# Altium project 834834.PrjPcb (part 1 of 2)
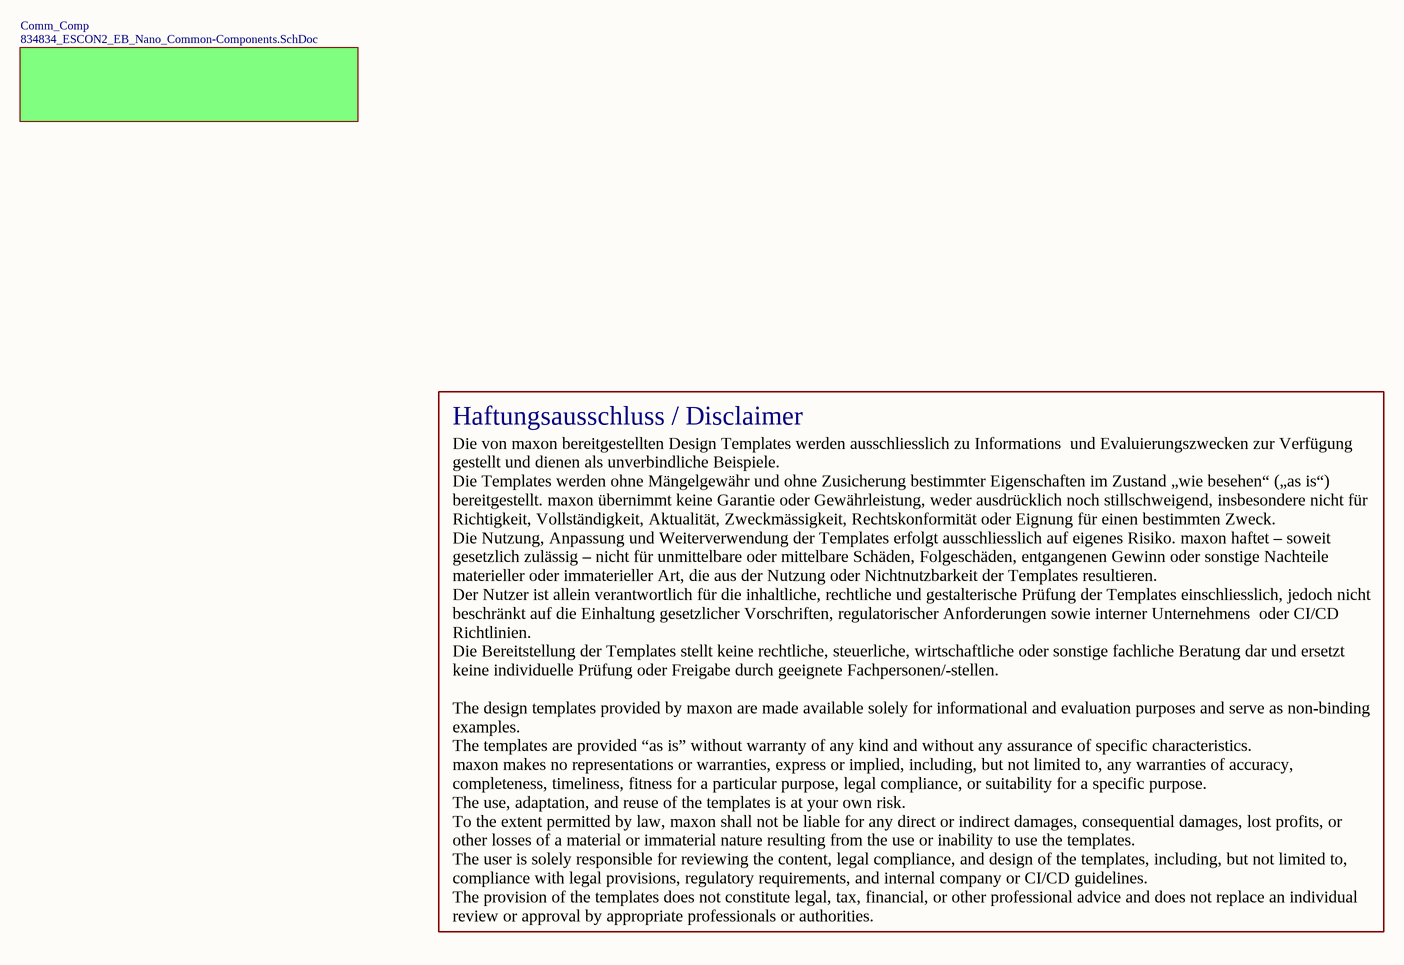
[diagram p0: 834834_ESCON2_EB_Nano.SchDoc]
PCB_raw: 834834-02; PCB unassembled: 834834; PCB Eng Rev: 02; Department: CCMC; CO_no: A100028401
4 sheets, 294 parts. Net scope: hierarchical (ports join the sheet entries above them; power ports are global).
Board file: ESCON2 EB Nano.PcbDoc
Sheets:
  834834_ESCON2_EB_Nano.SchDoc
    Comm_Comp = 834834_ESCON2_EB_Nano_Common-Components.SchDoc
      Nano_Comp = 834834_ESCON2_EB_Nano_Nano-Components.SchDoc
        Nano_CAN_RS422 = 834834_ESCON2_EB_Nano_Nano-CAN-RS422.SchDoc

## Sheet 834834_ESCON2_EB_Nano.SchDoc
size A3; SheetNumber: 1; SheetTotal: 4; Created: MMAGHIN; Modified: MMAGHIN; Reviewed: MMAGWAH; CreatedDate: 10.07.2023; ReviewedDate: 06.05.2024; ModifiedDate1: 29.04.2024

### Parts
*?  Disclaimer  (value not drawn)  (graphical)

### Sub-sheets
Comm_Comp = 834834_ESCON2_EB_Nano_Common-Components.SchDoc: no entries

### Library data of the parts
*? = CMP-002918-3: Disclaimer Text according to IFS-Doc:13538260

## Sheet 834834_ESCON2_EB_Nano_Common-Components.SchDoc
size A3; SheetNumber: 2; SheetTotal: 4; Created: MMAGHIN; Modified: MMAGHIN; Reviewed: MMAGWAH; CreatedDate: 10.07.2023; ReviewedDate: 06.05.2024; ModifiedDate1: 13.03.2024
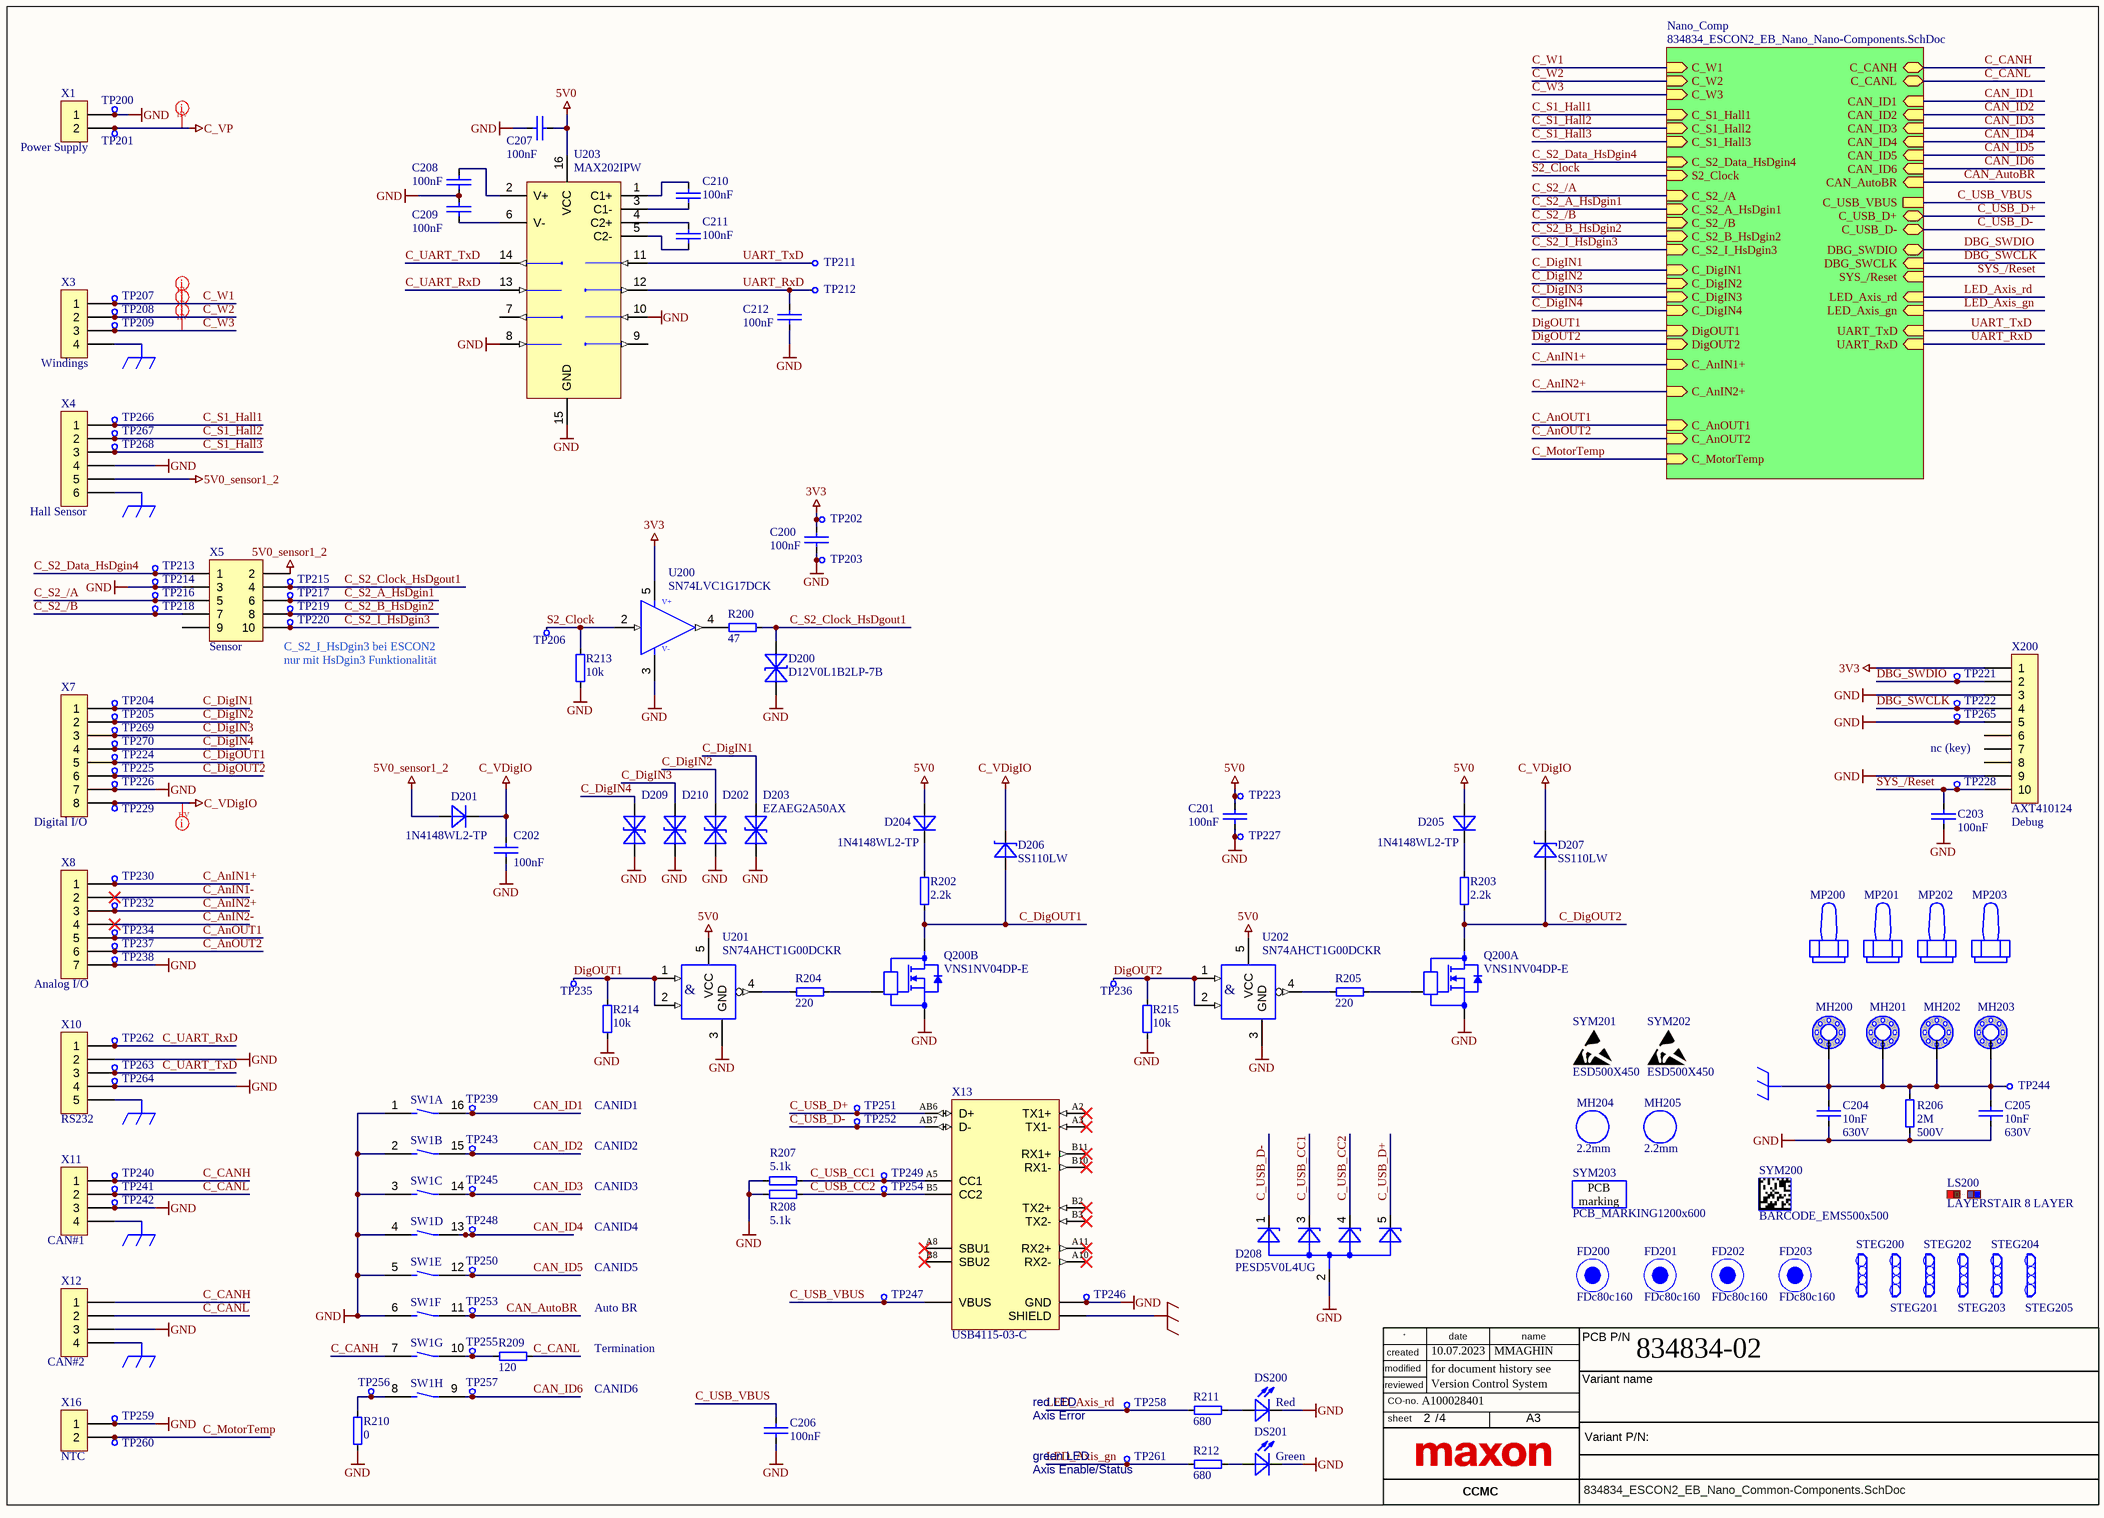
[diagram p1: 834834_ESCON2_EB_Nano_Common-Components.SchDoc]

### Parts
C200  value 100nF  [CAPC100X50X70L25N]  (hidden comment: 0402 100nF)
C201  value 100nF  [CAPC100X50X70L25N]  (hidden comment: 0402 100nF)
C202  value 100nF  [CAPC100X50X70L25N]  (hidden comment: 0402 100nF)
C203  value 100nF  [CAPC100X50X70L25N]  (hidden comment: 0402 100nF)
C204  value 10nF  Maximum Working Voltage: 630V  [CAPC200X125X150L47N]  (hidden comment: C0805C103KBRACAUTO)
C205  value 10nF  Maximum Working Voltage: 630V  [CAPC200X125X150L47N]  (hidden comment: C0805C103KBRACAUTO)
C206  value 100nF  [CAPC100X50X70L25N]  (hidden comment: 0402 100nF)
C207  value 100nF  [CAPC100X50X70L25N]  (hidden comment: 0402 100nF)
C208  value 100nF  [CAPC100X50X70L25N]  (hidden comment: 0402 100nF)
C209  value 100nF  [CAPC100X50X70L25N]  (hidden comment: 0402 100nF)
C210  value 100nF  [CAPC100X50X70L25N]  (hidden comment: 0402 100nF)
C211  value 100nF  [CAPC100X50X70L25N]  (hidden comment: 0402 100nF)
C212  value 100nF  [CAPC100X50X70L25N]  (hidden comment: 0402 100nF)
D200  D12V0L1B2LP-7B  [DIONPDFN2_102X60X60L25X50N]
D201  1N4148WL2-TP  [DIODFN2_102X60X60L25X50N]
D202  EZAEG2A50AX  [DIONPC105X53X43L26N]
D203  EZAEG2A50AX  [DIONPC105X53X43L26N]  (value not drawn)
D204  1N4148WL2-TP  [DIODFN2_102X60X60L25X50N]
D205  1N4148WL2-TP  [DIODFN2_102X60X60L25X50N]
D206  SS110LW  [SODFL359X170X143L65X95N]
D207  SS110LW  [SODFL359X170X143L65X95N]
D208  PESD5V0L4UG  [SOT23-5P65_210X110L28X20N]
D209  EZAEG2A50AX  [DIONPC105X53X43L26N]  (value not drawn)
D210  EZAEG2A50AX  [DIONPC105X53X43L26N]  (value not drawn)
DS200  Color(s): Red  [LEDSC80X160X90L45N_RED]  (hidden comment: 598-8010-107F)
DS201  Color(s): Green  [LEDSC80X160X90L45N_GREEN]  (hidden comment: 598-8070-107F)
FD200  FDc80c160  [FIDUCIAL_c80_c160]  (no BOM)
FD201  FDc80c160  [FIDUCIAL_c80_c160]  (no BOM)
FD202  FDc80c160  [FIDUCIAL_c80_c160]  (no BOM)
FD203  FDc80c160  [FIDUCIAL_c80_c160]  (no BOM)
LS200  LAYERSTAIR 8 LAYER  [8LS400X50w/oLETTERS_KEEPOUT]  (no BOM)
MH200  MTGNPH400A900V8H40_Snap-In_Spacer  [MTGNPH400A900V8H40_Snap-In_Spacer]  (value not drawn)  (no BOM)
MH201  MTGNPH400A900V8H40_Snap-In_Spacer  [MTGNPH400A900V8H40_Snap-In_Spacer]  (value not drawn)  (no BOM)
MH202  MTGNPH400A900V8H40_Snap-In_Spacer  [MTGNPH400A900V8H40_Snap-In_Spacer]  (value not drawn)  (no BOM)
MH203  MTGNPH400A900V8H40_Snap-In_Spacer  [MTGNPH400A900V8H40_Snap-In_Spacer]  (value not drawn)  (no BOM)
MH204  Diameter: 2.2mm  [MTGNPH220]  (hidden comment: MTGNPH220_NPTH)  (no BOM)
MH205  Diameter: 2.2mm  [MTGNPH220]  (hidden comment: MTGNPH220_NPTH)  (no BOM)
MP200  973100365  [WURTH_973100365]  (value not drawn)
MP201  973100365  [WURTH_973100365]  (value not drawn)
MP202  973100365  [WURTH_973100365]  (value not drawn)
MP203  973100365  [WURTH_973100365]  (value not drawn)
Q200  VNS1NV04DP-E  [SOIC8P127_490X599X175L83X41N]  (parts A,B of 2)
R200  value 47  [RESC100X52X40L22N]  (hidden comment: 0402 47R)
R202  value 2.2k  [RESC100X52X40L22N]  (hidden comment: 0402 2.2k)
R203  value 2.2k  [RESC100X52X40L22N]  (hidden comment: 0402 2.2k)
R204  value 220  [RESC100X52X40L22N]  (hidden comment: 0402 220R)
R205  value 220  [RESC100X52X40L22N]  (hidden comment: 0402 220R)
R206  value 2M  Maximum Working Voltage: 500V  [RESC320X160X90L47N]  (hidden comment: 1206 2M 500V)
R207  value 5.1k  [RESC100X52X40L22N]  (hidden comment: 0402 5.1k)
R208  value 5.1k  [RESC100X52X40L22N]  (hidden comment: 0402 5.1k)
R209  value 120  [RESC200X125X84L35N]  (hidden comment: 0805 120R)
R210  value 0  [RESC100X52X40L22N]  (hidden comment: 0402 0)
R211  value 680  [RESC100X52X40L22N]  (hidden comment: 0402 680R)
R212  value 680  [RESC100X52X40L22N]  (hidden comment: 0402 680R)
R213  value 10k  [RESC100X52X40L22N]  (hidden comment: 0402 10k)
R214  value 10k  [RESC100X52X40L22N]  (hidden comment: 0402 10k)
R215  value 10k  [RESC100X52X40L22N]  (hidden comment: 0402 10k)
STEG200  Steg400X90_7Hole  [Steg_400X90_7Hole]  (value not drawn)  (no BOM)
STEG201  Steg400X90_7Hole  [Steg_400X90_7Hole]  (value not drawn)  (no BOM)
STEG202  Steg400X90_7Hole  [Steg_400X90_7Hole]  (value not drawn)  (no BOM)
STEG203  Steg400X90_7Hole  [Steg_400X90_7Hole]  (value not drawn)  (no BOM)
STEG204  Steg400X90_7Hole  [Steg_400X90_7Hole]  (value not drawn)  (no BOM)
STEG205  Steg400X90_7Hole  [Steg_400X90_7Hole]  (value not drawn)  (no BOM)
SW1  DHN-08F-T-V  [SOIC16P127_1139X671X151L61X41N]  (value not drawn)  (parts A,B,C,D,E,F,G,H of 8)
SYM200  BARCODE_EMS500x500  [BARCODE_EMS_500x500]  (no BOM)
SYM201  ESD500X450  [ESD_copper_small]  (no BOM)
SYM202  ESD500X450  [ESD_copper_small]  (no BOM)
SYM203  PCB_MARKING1200x600  [MARKING_PCB_1200x600]  (no BOM)
TP200  TPc120  [TESTPOINT_c120]  (value not drawn)  (no BOM)
TP201  TPc120  [TESTPOINT_c120]  (value not drawn)  (no BOM)
TP202  TPc120  [TESTPOINT_c120]  (value not drawn)  (no BOM)
TP203  TPc120  [TESTPOINT_c120]  (value not drawn)  (no BOM)
TP204  TPc120  [TESTPOINT_c120]  (value not drawn)  (no BOM)
TP205  TPc120  [TESTPOINT_c120]  (value not drawn)  (no BOM)
TP206  TPc120  [TESTPOINT_c120]  (value not drawn)  (no BOM)
TP207  TPc120  [TESTPOINT_c120]  (value not drawn)  (no BOM)
TP208  TPc120  [TESTPOINT_c120]  (value not drawn)  (no BOM)
TP209  TPc120  [TESTPOINT_c120]  (value not drawn)  (no BOM)
TP211  TPc120  [TESTPOINT_c120]  (value not drawn)  (no BOM)
TP212  TPc120  [TESTPOINT_c120]  (value not drawn)  (no BOM)
TP213  TPc120  [TESTPOINT_c120]  (value not drawn)  (no BOM)
TP214  TPc120  [TESTPOINT_c120]  (value not drawn)  (no BOM)
TP215  TPc120  [TESTPOINT_c120]  (value not drawn)  (no BOM)
TP216  TPc120  [TESTPOINT_c120]  (value not drawn)  (no BOM)
TP217  TPc120  [TESTPOINT_c120]  (value not drawn)  (no BOM)
TP218  TPc120  [TESTPOINT_c120]  (value not drawn)  (no BOM)
TP219  TPc120  [TESTPOINT_c120]  (value not drawn)  (no BOM)
TP220  TPc120  [TESTPOINT_c120]  (value not drawn)  (no BOM)
TP221  TPc120  [TESTPOINT_c120]  (value not drawn)  (no BOM)
TP222  TPc120  [TESTPOINT_c120]  (value not drawn)  (no BOM)
TP223  TPc120  [TESTPOINT_c120]  (value not drawn)  (no BOM)
TP224  TPc120  [TESTPOINT_c120]  (value not drawn)  (no BOM)
TP225  TPc120  [TESTPOINT_c120]  (value not drawn)  (no BOM)
TP226  TPc120  [TESTPOINT_c120]  (value not drawn)  (no BOM)
TP227  TPc120  [TESTPOINT_c120]  (value not drawn)  (no BOM)
TP228  TPc120  [TESTPOINT_c120]  (value not drawn)  (no BOM)
TP229  TPc120  [TESTPOINT_c120]  (value not drawn)  (no BOM)
TP230  TPc120  [TESTPOINT_c120]  (value not drawn)  (no BOM)
TP232  TPc120  [TESTPOINT_c120]  (value not drawn)  (no BOM)
TP234  TPc120  [TESTPOINT_c120]  (value not drawn)  (no BOM)
TP235  TPc120  [TESTPOINT_c120]  (value not drawn)  (no BOM)
TP236  TPc120  [TESTPOINT_c120]  (value not drawn)  (no BOM)
TP237  TPc120  [TESTPOINT_c120]  (value not drawn)  (no BOM)
TP238  TPc120  [TESTPOINT_c120]  (value not drawn)  (no BOM)
TP239  TPc120  [TESTPOINT_c120]  (value not drawn)  (no BOM)
TP240  TPc120  [TESTPOINT_c120]  (value not drawn)  (no BOM)
TP241  TPc120  [TESTPOINT_c120]  (value not drawn)  (no BOM)
TP242  TPc120  [TESTPOINT_c120]  (value not drawn)  (no BOM)
TP243  TPc120  [TESTPOINT_c120]  (value not drawn)  (no BOM)
TP244  TPc120  [TESTPOINT_c120]  (value not drawn)  (no BOM)
TP245  TPc120  [TESTPOINT_c120]  (value not drawn)  (no BOM)
TP246  TPc120  [TESTPOINT_c120]  (value not drawn)  (no BOM)
TP247  TPc120  [TESTPOINT_c120]  (value not drawn)  (no BOM)
TP248  TPc120  [TESTPOINT_c120]  (value not drawn)  (no BOM)
TP249  TPc120  [TESTPOINT_c120]  (value not drawn)  (no BOM)
TP250  TPc120  [TESTPOINT_c120]  (value not drawn)  (no BOM)
TP251  TPc120  [TESTPOINT_c120]  (value not drawn)  (no BOM)
TP252  TPc120  [TESTPOINT_c120]  (value not drawn)  (no BOM)
TP253  TPc120  [TESTPOINT_c120]  (value not drawn)  (no BOM)
TP254  TPc120  [TESTPOINT_c120]  (value not drawn)  (no BOM)
TP255  TPc120  [TESTPOINT_c120]  (value not drawn)  (no BOM)
TP256  TPc120  [TESTPOINT_c120]  (value not drawn)  (no BOM)
TP257  TPc120  [TESTPOINT_c120]  (value not drawn)  (no BOM)
TP258  TPc120  [TESTPOINT_c120]  (value not drawn)  (no BOM)
TP259  TPc120  [TESTPOINT_c120]  (value not drawn)  (no BOM)
TP260  TPc120  [TESTPOINT_c120]  (value not drawn)  (no BOM)
TP261  TPc120  [TESTPOINT_c120]  (value not drawn)  (no BOM)
TP262  TPc120  [TESTPOINT_c120]  (value not drawn)  (no BOM)
TP263  TPc120  [TESTPOINT_c120]  (value not drawn)  (no BOM)
TP264  TPc120  [TESTPOINT_c120]  (value not drawn)  (no BOM)
TP265  TPc120  [TESTPOINT_c120]  (value not drawn)  (no BOM)
TP266  TPc120  [TESTPOINT_c120]  (value not drawn)  (no BOM)
TP267  TPc120  [TESTPOINT_c120]  (value not drawn)  (no BOM)
TP268  TPc120  [TESTPOINT_c120]  (value not drawn)  (no BOM)
TP269  TPc120  [TESTPOINT_c120]  (value not drawn)  (no BOM)
TP270  TPc120  [TESTPOINT_c120]  (value not drawn)  (no BOM)
U200  SN74LVC1G17DCK  [SOT23-5P65_210X110L28X20N]
U201  SN74AHCT1G00DCKR  [SOT23-5P65_210X110L28X20N]
U202  SN74AHCT1G00DCKR  [SOT23-5P65_210X110L28X20N]
U203  MAX202IPW  [SOP16P65_500X640X120L83X24N]
X1  39281023  [MOLEX_460150202]  (value not drawn)
X3  39281043  [MOLEX_460150402]  (value not drawn)
X4  430450612  [MOLEX_ 430450612]  (value not drawn)
X5  52601-S10-8LF  [AMPHENOL_52601-S10-8LF]  (value not drawn)
X7  5025840860  [MOLEX_5025840860]  (value not drawn)
X8  5025840760  [MOLEX_5025840760]  (value not drawn)
X10  RS232  [MOLEX_5025840560]
X11  5025840460  [MOLEX_5025840460]  (value not drawn)
X12  5025840460  [MOLEX_5025840460]  (value not drawn)
X13  USB4115-03-C  [GTC_USB4115-03-C]
X16  430450212  [MOLEX_ 430450212]  (value not drawn)
X200  AXT410124  [PANASONIC_AXT410124]

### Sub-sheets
Nano_Comp = 834834_ESCON2_EB_Nano_Nano-Components.SchDoc: C_W1 (in), C_W2 (in), C_W3 (in), C_S1_Hall1 (in), C_S1_Hall2 (in), C_S1_Hall3 (in), C_S2_Data_HsDgin4 (in), S2_Clock (in), C_S2_A_HsDgin1 (in), C_S2_B_HsDgin2 (in), C_S2_I_HsDgin3 (in), C_DigIN1 (in), C_DigIN2 (in), C_DigIN3 (in), C_DigIN4 (in), DigOUT1 (in), DigOUT2 (in), C_AnIN1+ (in), C_AnIN2+ (in), C_AnOUT1 (in), C_AnOUT2 (in), C_CANH (bidir), C_CANL (bidir), CAN_ID1 (in), CAN_ID2 (in), CAN_ID3 (in), CAN_ID4 (in), CAN_ID5 (in), CAN_ID6 (in), CAN_AutoBR (in), C_USB_VBUS, C_USB_D+ (bidir), C_USB_D- (bidir), DBG_SWDIO (bidir), DBG_SWCLK (in), SYS_/Reset (in), UART_TxD (in), UART_RxD (in), LED_Axis_rd (in), LED_Axis_gn (in), C_MotorTemp (in), C_S2_/B (in), C_S2_/A (in)

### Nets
3V3: C200.2 TP202.1 U200.5(VCC) X200.1
5V0: C201.2 C207.1 D204.2(A) D205.2(A) TP223.1 U201.5(VCC) U202.5(VCC) U203.16(VCC)
5V0_sensor1_2: D201.2(A) X4.5 X5.2
C_VDigIO: C202.2 D201.1(C) D206.1(C) D207.1(C) TP229.1 X7.8
C_VP: TP201.1 X1.2
GND: C200.1 C201.1 C202.1 C203.1 C204.1 C205.1 C206.1 C207.2 C208.1 C209.2 C212.1 D200.1 D202.1 D203.1 D208.2(A) D209.1 D210.1 DS200.1(C) DS201.1(C) Q200.1(S1) Q200.3(S2) R206.1 R207.2 R208.2 R210.1 R213.1 R214.1 R215.1 SW1.1 SW1.2 SW1.3 SW1.4 SW1.5 SW1.6 TP200.1 TP203.1 TP214.1 TP226.1 TP227.1 TP238.1 TP242.1 TP246.1 TP259.1 TP264.1 TP265.1 U200.3(GND) U201.3(GND) U202.3(GND) U203.8(RIN2) U203.10(DIN2) U203.15(GND) X1.1 X4.4 X5.3 X7.7 X8.7 X10.2 X10.4 X11.3 X12.3 X13.AB112(GND) X16.1 X200.3 X200.5 X200.9
SGND: C204.2 C205.2 MH200.1 MH201.1 MH202.1 MH203.1 R206.2 TP244.1 X3.4 X4.6 X10.5 X11.4 X12.4 X13.SHIELD
C_AnIN1+: TP230.1 X8.1 ; sheet Nano_Comp/C_AnIN1+
C_AnIN1-: X8.2
C_AnIN2+: TP232.1 X8.3 ; sheet Nano_Comp/C_AnIN2+
C_AnIN2-: X8.4
C_AnOUT1: TP234.1 X8.5 ; sheet Nano_Comp/C_AnOUT1
C_AnOUT2: TP237.1 X8.6 ; sheet Nano_Comp/C_AnOUT2
C_CANH: SW1.7 TP240.1 X11.1 X12.1 ; sheet Nano_Comp/C_CANH
C_CANL: R209.2 TP241.1 X11.2 X12.2 ; sheet Nano_Comp/C_CANL
C_DigIN1: D203.2 TP204.1 X7.1 ; sheet Nano_Comp/C_DigIN1
C_DigIN2: D202.2 TP205.1 X7.2 ; sheet Nano_Comp/C_DigIN2
C_DigIN3: D210.2 TP269.1 X7.3 ; sheet Nano_Comp/C_DigIN3
C_DigIN4: D209.2 TP270.1 X7.4 ; sheet Nano_Comp/C_DigIN4
C_DigOUT1: D206.2(A) Q200.5(D2) R202.1 TP224.1 X7.5
C_DigOUT2: D207.2(A) Q200.6(D1) R203.1 TP225.1 X7.6
C_MotorTemp: TP260.1 X16.2 ; sheet Nano_Comp/C_MotorTemp
C_S1_Hall1: TP266.1 X4.1 ; sheet Nano_Comp/C_S1_Hall1
C_S1_Hall2: TP267.1 X4.2 ; sheet Nano_Comp/C_S1_Hall2
C_S1_Hall3: TP268.1 X4.3 ; sheet Nano_Comp/C_S1_Hall3
C_S2_/A: TP216.1 X5.5 ; sheet Nano_Comp/C_S2_/A
C_S2_/B: TP218.1 X5.7 ; sheet Nano_Comp/C_S2_/B
C_S2_A_HsDgin1: TP217.1 X5.6 ; sheet Nano_Comp/C_S2_A_HsDgin1
C_S2_B_HsDgin2: TP219.1 X5.8 ; sheet Nano_Comp/C_S2_B_HsDgin2
C_S2_Clock_HsDgout1: D200.2 R200.2 TP215.1 X5.4
C_S2_Data_HsDgin4: TP213.1 X5.1 ; sheet Nano_Comp/C_S2_Data_HsDgin4
C_S2_I_HsDgin3: TP220.1 X5.10 ; sheet Nano_Comp/C_S2_I_HsDgin3
C_UART_RxD: TP262.1 U203.13(RIN1) X10.1
C_UART_TxD: TP263.1 U203.14(DOUT1) X10.3
C_USB_CC1: D208.3 R207.1 TP249.1 X13.A5(CC1)
C_USB_CC2: D208.4 R208.1 TP254.1 X13.B5(CC2)
C_USB_D+: D208.5 TP251.1 X13.AB6(D+) ; sheet Nano_Comp/C_USB_D+
C_USB_D-: D208.1 TP252.1 X13.AB7(D-) ; sheet Nano_Comp/C_USB_D-
C_USB_VBUS: C206.2 TP247.1 X13.AB49(VBUS) ; sheet Nano_Comp/C_USB_VBUS
C_W1: TP207.1 X3.1 ; sheet Nano_Comp/C_W1
C_W2: TP208.1 X3.2 ; sheet Nano_Comp/C_W2
C_W3: TP209.1 X3.3 ; sheet Nano_Comp/C_W3
CAN_AutoBR: SW1.11 TP253.1 ; sheet Nano_Comp/CAN_AutoBR
CAN_ID1: SW1.16 TP239.1 ; sheet Nano_Comp/CAN_ID1
CAN_ID2: SW1.15 TP243.1 ; sheet Nano_Comp/CAN_ID2
CAN_ID3: SW1.14 TP245.1 ; sheet Nano_Comp/CAN_ID3
CAN_ID4: SW1.13 TP248.1 ; sheet Nano_Comp/CAN_ID4
CAN_ID5: SW1.12 TP250.1 ; sheet Nano_Comp/CAN_ID5
CAN_ID6: SW1.9 TP257.1 ; sheet Nano_Comp/CAN_ID6
DBG_SWCLK: TP222.1 X200.4 ; sheet Nano_Comp/DBG_SWCLK
DBG_SWDIO: TP221.1 X200.2 ; sheet Nano_Comp/DBG_SWDIO
DigOUT1: R214.2 TP235.1 U201.1(inA) U201.2(inB) ; sheet Nano_Comp/DigOUT1
DigOUT2: R215.2 TP236.1 U202.1(inA) U202.2(inB) ; sheet Nano_Comp/DigOUT2
LED_Axis_gn: R212.1 TP261.1 ; sheet Nano_Comp/LED_Axis_gn
LED_Axis_rd: R211.1 TP258.1 ; sheet Nano_Comp/LED_Axis_rd
S2_Clock: R213.2 TP206.1 U200.2(inA) ; sheet Nano_Comp/S2_Clock
SYS_/Reset: C203.2 TP228.1 X200.10 ; sheet Nano_Comp/SYS_/Reset
UART_RxD: C212.2 TP212.1 U203.12(ROUT1) ; sheet Nano_Comp/UART_RxD
UART_TxD: TP211.1 U203.11(DIN1) ; sheet Nano_Comp/UART_TxD
NetC208_2: C208.2 U203.2(V+)
NetC209_1: C209.1 U203.6(V-)
NetC210_1: C210.1 U203.1(C1+)
NetC210_2: C210.2 U203.3(C1-)
NetC211_1: C211.1 U203.4(C2+)
NetC211_2: C211.2 U203.5(C2-)
NetD204_1: D204.1(C) R202.2
NetD205_1: D205.1(C) R203.2
NetDS200_2: DS200.2(A) R211.2
NetDS201_2: DS201.2(A) R212.2
NetQ200_2: Q200.2(IN1) R205.2
NetQ200_4: Q200.4(IN2) R204.2
NetR200_1: R200.1 U200.4(outY)
NetR204_1: R204.1 U201.4(outY)
NetR205_1: R205.1 U202.4(outY)
NetR209_1: R209.1 SW1.10 TP255.1
NetR210_2: R210.2 SW1.8 TP256.1

Not connected (* = marked no-connect by the designer): U203 7(DOUT2) 9(ROUT2); X5 9; X13 A2(TX1+)* A3(TX1-)* A8(SBU1)* A10(RX2-)* A11(RX2+)* B2(TX2+)* B3(TX2-)* B8(SBU2)* B10(RX1-)* B11(RX1+)*; X200 6 7 8

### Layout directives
net class HV: C_VDigIO, C_VP, C_W1, C_W2, C_W3

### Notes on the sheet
- Power Supply
- (near X3) Windings
- (near X4) Hall Sensor
- (near X5) Sensor
- C_S2_I_HsDgin3 bei ESCON2
- nur mit HsDgin3 Funktionalität
- nc (key)
- Digital I/O
- (near X200) Debug
- (near X8) Analog I/O
- CANID1
- CANID2
- CANID3
- (near X11) CAN#1
- CANID4
- CANID5
- Auto BR
- (near X12) CAN#2
- CANID6
- Termination
- (near X16) NTC
- red LED
- Axis Error
- green LED
- Axis Enable/Status

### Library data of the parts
C200 C201 C203 C207-C212 = CMP-000709-3: 100nF X7R >=16V 20%; Part Number: Ceramic, 0402, 100nF, 20%, >=16V, X7R, @, Soft Termination: N, -55°C to 125°C; Manufacturer: X; Maximum Working Voltage: 16V; Soft Termination: N; Case (Metric): 1005
C202 C206 = CMP-001306-1: 100nF X7R >=50V 20%; Part Number: Ceramic, 0402, 100nF, 20%, >=50V, X7R, @, Soft Termination: N, -55°C to 125°C; Manufacturer: X; Soft Termination: N; Case (Metric): 1005; Maximum Working Voltage: 50V
C204 C205 = CMP-000937-4: 10nF X7R >=630V 20%; Manufacturer: Murata; Dielectric Withstanding Voltage: > 850V 1sec; Case (Metric): 2012; Soft Termination: N
D200 = CMP-001106-5: Transient Voltage Suppressor Diode, 12V V(RWM), Bidirectional, 100W, 1 Element, SOD-882/DFN1006; Manufacturer: Diodes; Element Configuration: Single; Breakdown Voltage: 13V; Polarity: Bipolar
D201 D204 D205 = CMP-000606-13: Diode Switching, >=70V, >=150mA, SOD882/DFN1006/0402/SOD-923F; Manufacturer: MCC; Polarity: Unipolar; Recovery time: 4ns; Reverse Voltage: 70V; Element Configuration: Single; RMS Current: 150mA
D202 D203 D209 D210 = CMP-000066-17: Transient Voltage Suppressor Diode, 30V V(RWM), Bidirectional, ESD, 1 Element, 0402; Manufacturer: Panasonic; Element Configuration: Single; Polarity: Bipolar
D206 D207 = CMP-000633-9: Schottky Diode, >=90V, >=1A, SOD-123FL/SOD-123W; Manufacturer: Taiwan Semiconductor; RMS Current: 1A; Polarity: Unipolar; Reverse Voltage: 90V; Element Configuration: Single
D208 = CMP-000635-10: Transient Voltage Suppressor Diode, 4-Line, 5V V(RWM), Unidirectional, 30W, 4 Element , SOT353/SC-88A; Manufacturer: Nexperia; Min Breakdown Voltage: 6.46V; Nummber of Pins: 5; Element Configuration: Array; Common Anode; Max Junction Temperature: 150°C; Polarity: Unipolar; Breakdown Voltage: 6.8V; Nummber of Elements: 4; Max Breakdown Voltage: 7.14V; Clamping Voltage: 12V
DS200 = CMP-000723-7: Single Color Chip LED, red, 0603; Manufacturer: Dialight; Luminous Intensity: >5mcd@20mA; Wavelength: 617-640nm
DS201 = CMP-000722-6: Single Color Chip LED, green, 0603; Manufacturer: Dialight; Luminous Intensity: >5mcd@20mA; Wavelength: 564...575nm
FD200-FD203 = CMP-000010-5: Fiducial, Global, Round; 0.80 mm D, 1.60 mm Clearance
LS200 = CMP-001088-3: Layer Stair 8 Layer
MH200-MH203 = CMP-001801-1: Mounting Hole, Non-Plated; 9.00 mm Clearance, 4.00 mm Hole (with 8 vias), for 4mm Dia. Snap-In Spacer; pin to pad: 1>2+3+4+5+6+7+8+9; Metric screw: 4mm Dia Snap-In Spacer; Wave: X
MH204 MH205 = CMP-001004-5: Mounting Hole, Non-Plated; 0.00 mm Clearance, 2.20 mm Hole
MP200-MP203 = CMP-001759-4: WA-SNTI Plastic Spacer Stud, D=4.0mm, L=10mm, M3, SW=6; Min PCB Thickness: 1.8mm; Max PCB Thickness: 2.1mm; Mounting Hole Diameter: 4.00mm; Stand-Off Height: 10mm; Stand-Off Outside Size: SW6; Connection Style PCB Side: Snap; Connection Diameter PCB Side: 4.0mm; Connection Style Far Side: Female; Connection Length Far Side: 5mm; Stand-Off Outside Style: Hex; Connection Length PCB Side: 9.5mm
Q200 = CMP-001108-5: N-Channel MOSFET, Self Protected, 36V, 0.5ohm, SO-8; pin to pad: 5>5+6 6>7+8; Manufacturer: ST Microelectronics; Element Configuration: N-CH, Self Protected
R200 = CMP-000161-11: 47R 1% 62.5mW 100ppm; Part Number: Thick-Film, 0402, 47, 1%, 62.5mW@70°C, 50V, 100ppm, -55°C to 155°C; Manufacturer: X; Max Junction Temperature: 155°C; AECQ: N; Case (Metric): 1050; Power Rating Temperature: 70°C; Maximum Working Voltage: 50V; Maximum Overload Voltage: 100V
R202 R203 = CMP-000197-11: 2.2k 1% 62.5mW 100ppm; Part Number: Thick-Film, 0402, 2.2k, 1%, 62.5mW@70°C, 50V, 100ppm, -55°C to 155°C; Manufacturer: X; Max Junction Temperature: 155°C; AECQ: N; Case (Metric): 1050; Power Rating Temperature: 70°C; Maximum Working Voltage: 50V; Maximum Overload Voltage: 100V
R204 R205 = CMP-000173-11: 220R 1% 62.5mW 100ppm; Part Number: Thick-Film, 0402, 220, 1%, 62.5mW@70°C, 50V, 100ppm, -55°C to 155°C; Manufacturer: X; Max Junction Temperature: 155°C; AECQ: N; Case (Metric): 1050; Power Rating Temperature: 70°C; Maximum Working Voltage: 50V; Maximum Overload Voltage: 100V
R206 = CMP-000935-4: 2M 5% 250mW 200ppm >=500V; Manufacturer: X; Part Number: Thick-Film, 1206, 2M, 5%, 250mW@70°C, 500V, 200ppm, -55°C to 155°C; AECQ: N; Case (Metric): 3216; Maximum Overload Voltage: 1kV; Power Rating Temperature: 70°C; Max Junction Temperature: 155°C
R207 R208 = CMP-000206-11: 5.1k 1% 62.5mW 100ppm; Part Number: Thick-Film, 0402, 5.1k, 1%, 62.5mW@70°C, 50V, 100ppm, -55°C to 155°C; Manufacturer: X; Max Junction Temperature: 155°C; AECQ: N; Case (Metric): 1050; Power Rating Temperature: 70°C; Maximum Working Voltage: 50V; Maximum Overload Voltage: 100V
R209 = CMP-000325-10: 120R 1% 125mW 100ppm; Part Number: Thick-Film, 0805, 120, 1%, 125mW@70°C, 150V, 100ppm, -55°C to 155°C; Manufacturer: X; Max Junction Temperature: 155°C; AECQ: N; Case (Metric): 2012; Power Rating Temperature: 70°C; Maximum Working Voltage: 150V; Maximum Overload Voltage: 300V
R210 = CMP-000466-10: 0R Jumper; Part Number: Thick-Film, 0402, 0, -55°C to 155°C; Manufacturer: X; Case (Metric): 1050; RMS Current: 1A; Maximum Overload Voltage: 100V; Max Junction Temperature: 155°C; Maximum Working Voltage: 50V
R211 R212 = CMP-000185-11: 680R 1% 62.5mW 100ppm; Part Number: Thick-Film, 0402, 680, 1%, 62.5mW@70°C, 50V, 100ppm, -55°C to 155°C; Manufacturer: X; Max Junction Temperature: 155°C; AECQ: N; Case (Metric): 1050; Power Rating Temperature: 70°C; Maximum Working Voltage: 50V; Maximum Overload Voltage: 100V
R213-R215 = CMP-000492-11: 10k 1% 62.5mW 100ppm; Part Number: Thick-Film, 0402, 10k, 1%, 62.5mW@70°C, 50V, 100ppm, -55°C to 155°C; Manufacturer: X; Max Junction Temperature: 155°C; AECQ: N; Case (Metric): 1050; Power Rating Temperature: 70°C; Maximum Working Voltage: 50V; Maximum Overload Voltage: 100V
STEG200-STEG205 = CMP-000007-5: Breakaway tabs; 4.00 mm L X 0.90 mm W, 7 Hole
SW1 = CMP-001031-3: Slide Dip Switch, 8 Switches, 0.025A, 24VDC, SMD; Manufacturer: Diptronics
SYM200 = CMP-001233-2: Barcode EMS; 5.0 x 5.0 mm
SYM201 SYM202 = CMP-000018-6: ESD-Sign; 5.0 mm L X 4.5 mm W
SYM203 = CMP-001854-7: PCB Marking; 12.0 x 6.0 mm
TP200-TP209 TP211-TP230 TP232 TP234-TP270 = CMP-000014-7: Test Point; 1 pin, 1.20 mm D
U200 = CMP-001041-6: Single buffer with Schmitt-Trigger inputs; Manufacturer: Texas Instruments; AECQ: N; Max Supply Voltage: 5.5V; Min Supply Voltage: 1.65V
U201 U202 = CMP-002037-1: Single, 2-Input NAND Gate, 5V; Min Supply Voltage: 4.5V; Max Supply Voltage: 5.5V
U203 = CMP-000646-4: RS-232 Line Transceiver, Dual channel 120kbps , 5.0V, TSSOP16; Manufacturer: Texas instruments; Max Supply Voltage: 5.5V; Min Supply Voltage: 4.5V
X1 = CMP-001018-6: Mini-Fit Jr. Vertical Header, 4.20mm Pitch, Dual Row, 2 Circuits, without Snap-in Plastic Peg PCB Lock, Tin, Natural; Number of Contacts: 2; Operating Voltage: 600V; Operating Current: 9A; System: Connector
X3 = CMP-001016-8: Mini-Fit Jr. Vertical Header, 4.20mm Pitch, Dual Row, 4 Circuits, without Snap-in Plastic Peg PCB Lock, Tin, Natural; Operating Current: 9A; Operating Voltage: 600V; Number of Contacts: 4; System: Connector
X4 = CMP-001098-6: Micro-Fit 3.0 Vertical Header, 3.00mm Pitch, Dual Row, 6 Circuits, with PCB Polarizing Peg, Black; Manufacturer: Molex; Operating Voltage: 600V; Number of Contacts: 6; Operating Current: 8.5A
X5 = CMP-001165-3: Header, 2.54mm Pitch, Dual Row, SMT, Vertical, 10 Circuits; Manufacturer: Amphenol; Operating Voltage: 500V; Number of Contacts: 10; Operating Current: 3A
X7 = CMP-001014-7: 1.50mm Pitch, CLIK-Mate PCB Receptacle, Single Row, Surface Mount, Tin Plating, Positive Lock, with Pick-and-Place Polyimide Tape, 8 Circuits, Beige; Manufacturer: Molex; Number of Contacts: 8; Operating Current: 2A; Operating Voltage: 100V
X8 = CMP-001015-7: 1.50mm Pitch, CLIK-Mate PCB Receptacle, Single Row, Surface Mount, Tin Plating, Positive Lock, with Pick-and-Place Polyimide Tape, 7 Circuits, Beige; Manufacturer: Molex; Operating Voltage: 100V; Operating Current: 2A; Number of Contacts: 7
X10 = CMP-001023-6: 1.50mm Pitch, CLIK-Mate PCB Receptacle, Single Row, Surface Mount, Tin Plating, Positive Lock, with Pick-and-Place Polyimide Tape, 5 Circuits, Beige; Manufacturer: Molex; Operating Current: 2A; Operating Voltage: 100V; Number of Contacts: 5
X11 X12 = CMP-001170-6: 1.50mm Pitch, CLIK-Mate PCB Receptacle, Single Row, Surface Mount, Tin Plating, Positive Lock, with Pick-and-Place Polyimide Tape, 4 Circuits, Beige; Manufacturer: Molex; Number of Contacts: 4; Operating Voltage: 100V; Operating Current: 2A
X13 = CMP-001110-10: USB Type C, SHLD, 24poles, vertical; pin to pad: AB6>A6+B6 AB7>A7+B7 AB49>A4+A9+B4+B9 AB112>B1+A12+B12+A1 SHIELD>S1+S2+S3+S4; Manufacturer: GTC
X16 = CMP-001107-4: Micro-Fit 3.0 Vertical Header, 3.00mm Pitch, Dual Row, 2 Circuits, with PCB Polarizing Peg, Black; Manufacturer: Molex; Operating Voltage: 600V; Number of Contacts: 2; Operating Current: 8.5A
X200 = CMP-001083-11: Board to Board Connector, 2*5 pole, SMD, 0.4mm pitch, 1.5mm stacking Height; Manufacturer: Panasonic; Number of Contacts: 10; Operating Current: 300mA; Operating Voltage: 60V

## Sheet 834834_ESCON2_EB_Nano_Nano-Components.SchDoc
size A3; SheetNumber: 3; SheetTotal: 4; Created: MMAGHIN; Modified: MMAGHIN; Reviewed: MMAGWAH; CreatedDate: 10.07.2023; ReviewedDate: 06.05.2024; ModifiedDate1: 29.04.2024
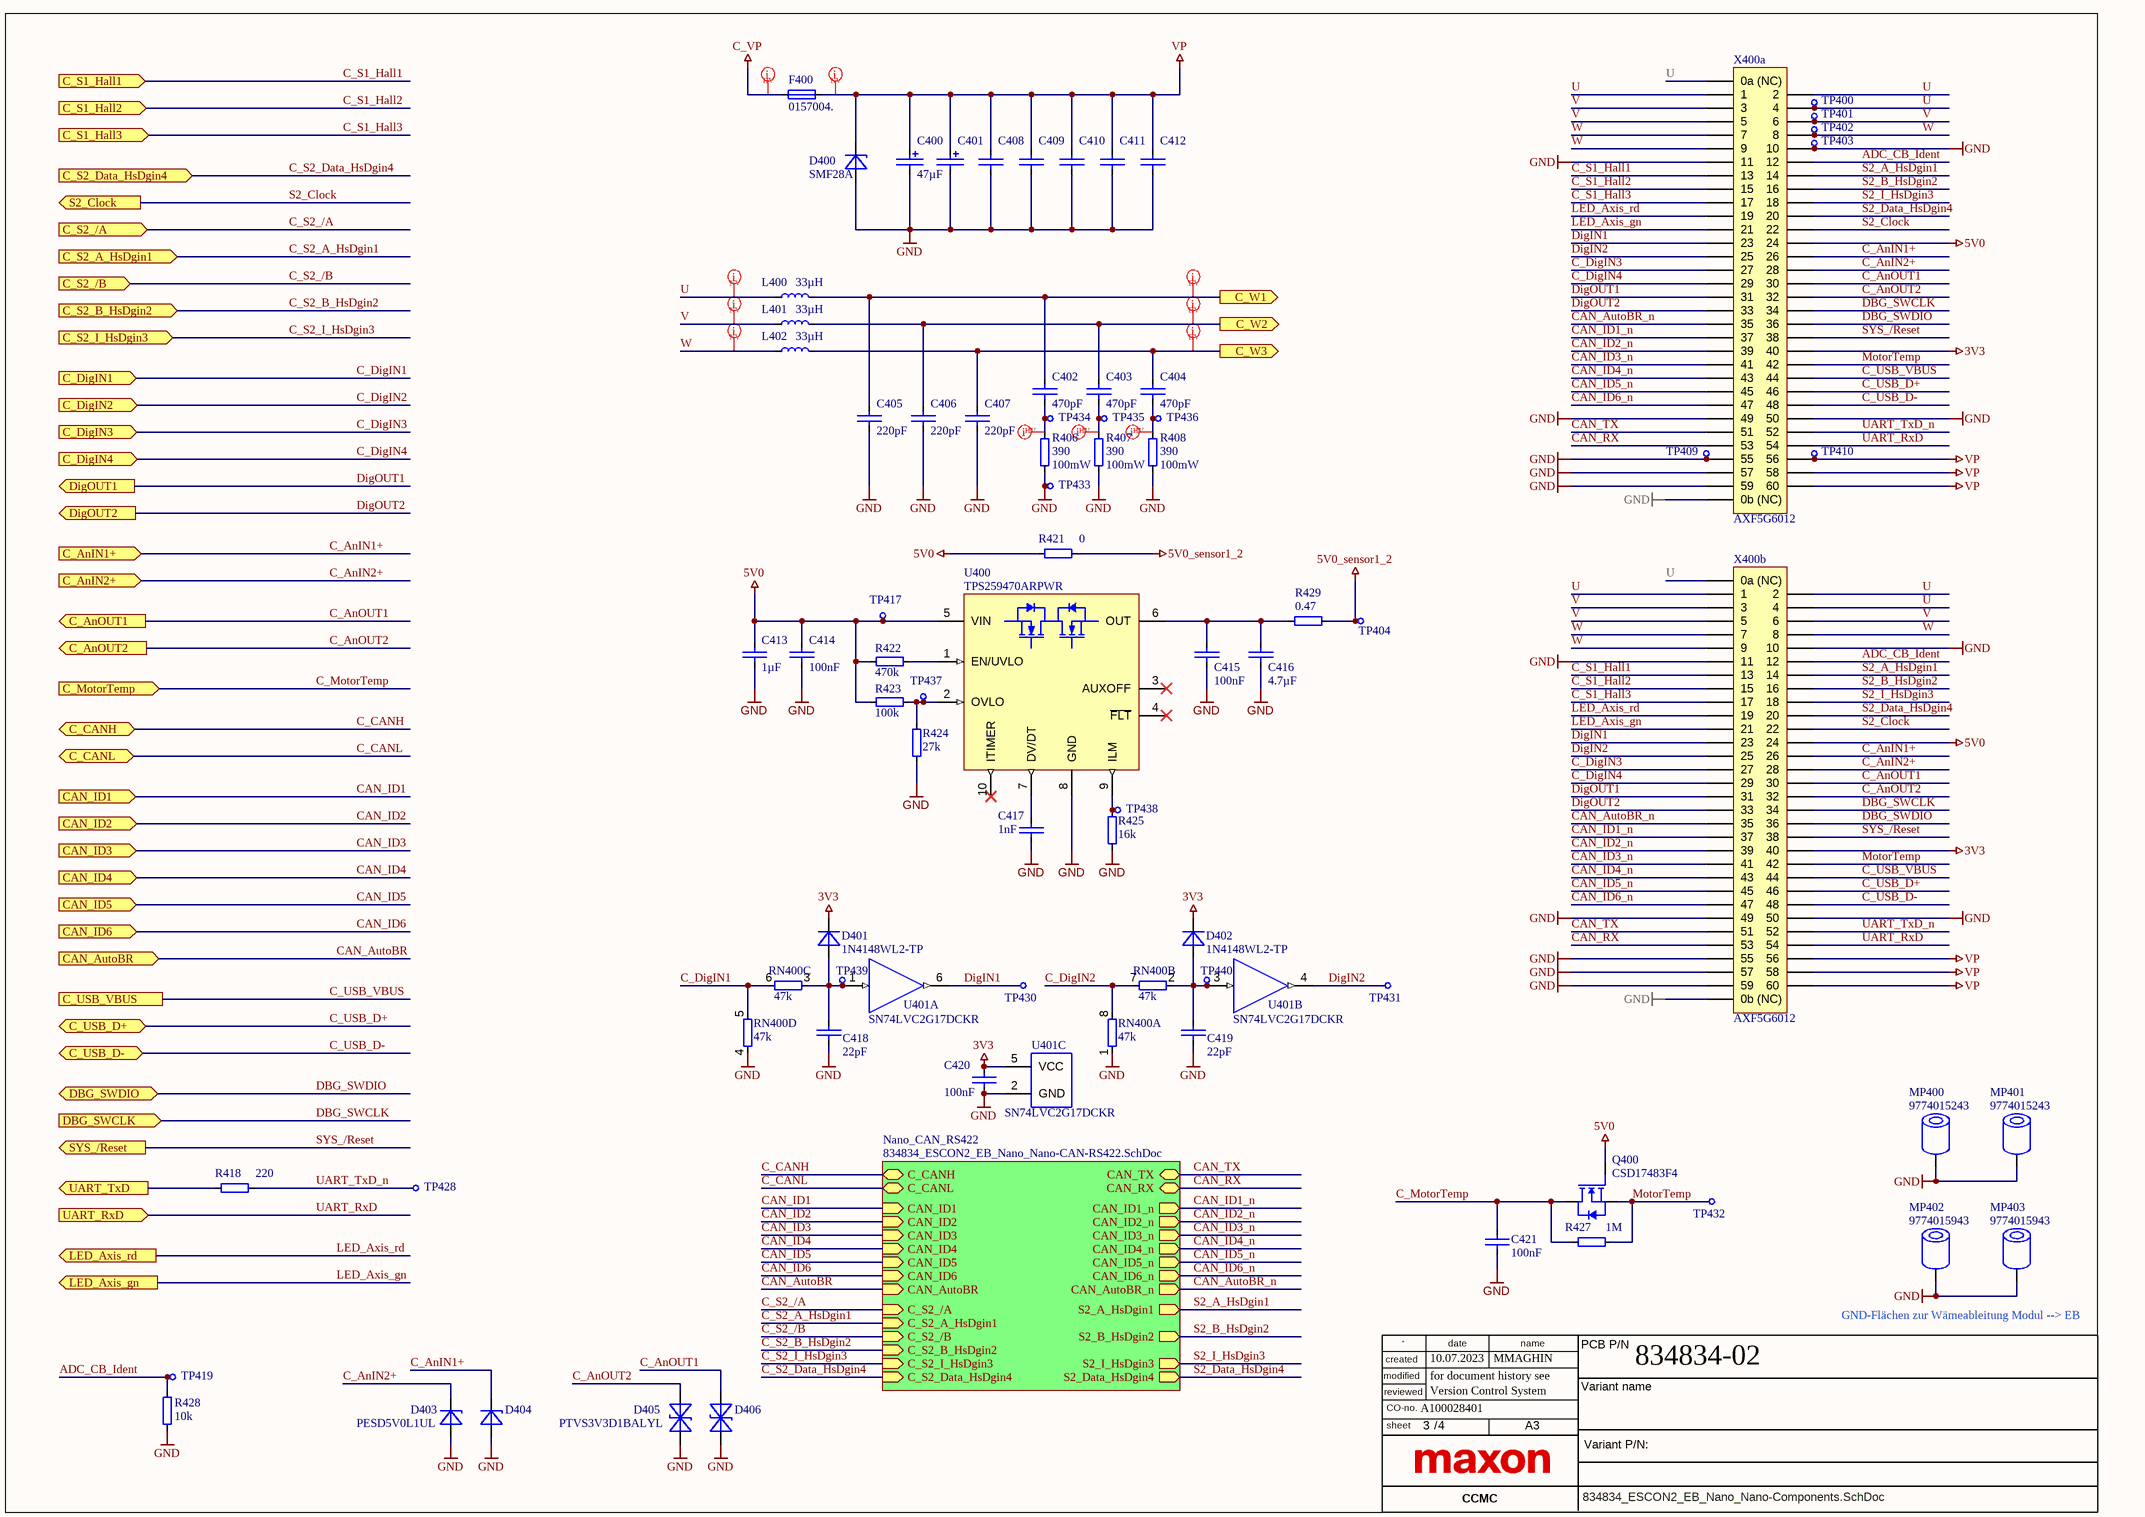
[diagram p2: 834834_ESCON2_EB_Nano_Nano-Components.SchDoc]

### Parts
C400  value 47µF  [PANASONIC_F_VIB]  (hidden comment: HHXC500ARA470MHA0G)
C401  HHXD630ARA220MF80G  [PANASONIC_D8_VIB]  (value not drawn)
C402  value 470pF  [CAPC100X50X70L25N]  (hidden comment: 0402 470pF)
C403  value 470pF  [CAPC100X50X70L25N]  (hidden comment: 0402 470pF)
C404  value 470pF  [CAPC100X50X70L25N]  (hidden comment: 0402 470pF)
C405  value 220pF  [CAPC100X50X70L25N]  (hidden comment: 0402 220pF)
C406  value 220pF  [CAPC100X50X70L25N]  (hidden comment: 0402 220pF)
C407  value 220pF  [CAPC100X50X70L25N]  (hidden comment: 0402 220pF)
C408  1206 4.7uF Soft Termination  [CAP320x160x190L60N]  (value not drawn)
C409  1206 4.7uF Soft Termination  [CAP320x160x190L60N]  (value not drawn)
C410  1206 4.7uF Soft Termination  [CAP320x160x190L60N]  (value not drawn)
C411  1206 4.7uF Soft Termination  [CAP320x160x190L60N]  (value not drawn)
C412  1206 4.7uF Soft Termination  [CAP320x160x190L60N]  (value not drawn)
C413  value 1µF  [CAPC160X80X100L35N]  (hidden comment: 0603 1uF)
C414  value 100nF  [CAPC100X50X70L25N]  (hidden comment: 0402 100nF)
C415  value 100nF  [CAPC100X50X70L25N]  (hidden comment: 0402 100nF)
C416  value 4.7µF  [CAPC200X125X150L47N]  (hidden comment: 0805 4.7uF)
C417  value 1nF  [CAPC100X50X70L25N]  (hidden comment: 0402 1nF)
C418  value 22pF  [CAPC100X50X70L25N]  (hidden comment: 0402 22pF)
C419  value 22pF  [CAPC100X50X70L25N]  (hidden comment: 0402 22pF)
C420  value 100nF  [CAPC100X50X70L25N]  (hidden comment: 0402 100nF)
C421  value 100nF  [CAPC100X50X70L25N]  (hidden comment: 0402 100nF)
D400  SMF28A  [SODFL359X170X143L65X95N]
D401  1N4148WL2-TP  [DIODFN2_102X60X60L25X50N]
D402  1N4148WL2-TP  [DIODFN2_102X60X60L25X50N]
D403  PESD5V0L1UL  [SODFL_DIODFN2_102X60X60L25X50L]
D404  PESD5V0L1UL  [SODFL_DIODFN2_102X60X60L25X50L]  (value not drawn)
D405  PTVS3V3D1BALYL  [DIONPDFN2_102X60X60L25X50N]
D406  PTVS3V3D1BALYL  [DIONPDFN2_102X60X60L25X50N]  (value not drawn)
F400  0157004.  [FUSC650X370X403L148N]
L400  value 33µH  [INDDFN2_800X800X420L232X630N]  (hidden comment: SRN8040TA-330M)
L401  value 33µH  [INDDFN2_800X800X420L232X630N]  (hidden comment: SRN8040TA-330M)
L402  value 33µH  [INDDFN2_800X800X420L232X630N]  (hidden comment: SRN8040TA-330M)
MP400  9774015243  [WURTH_9774015243_NPTH]
MP401  9774015243  [WURTH_9774015243_NPTH]
MP402  9774015943  [WURTH_9774015943_NPTH]
MP403  9774015943  [WURTH_9774015943_NPTH]
Q400  CSD17483F4  [TRXDFN3_101X61X53L25X15N]
R406  value 390  Power Rating: 100mW  [RESC160X82X65L30N]  (hidden comment: 0603 390R)
R407  value 390  Power Rating: 100mW  [RESC160X82X65L30N]  (hidden comment: 0603 390R)
R408  value 390  Power Rating: 100mW  [RESC160X82X65L30N]  (hidden comment: 0603 390R)
R418  value 220  [RESC100X52X40L22N]  (hidden comment: 0402 220R)
R421  value 0  [RESC100X52X40L22N]  (hidden comment: 0402 0)
R422  value 470k  [RESC100X52X40L22N]  (hidden comment: 0402 470k)
R423  value 100k  [RESC100X52X40L22N]  (hidden comment: 0402 100k)
R424  value 27k  [RESC100X52X40L22N]  (hidden comment: 0402 27k)
R425  value 16k  [RESC100X52X40L22N]  (hidden comment: 0402 16k)
R427  value 1M  [RESC100X52X40L22N]  (hidden comment: 0402 1M)
R428  value 10k  [RESC100X52X40L22N]  (hidden comment: 0402 10k)
R429  value 0.47  [RESC100X52X40L22N]  (hidden comment: 0402 0R47)
RN400  value 47k  [RESCAXS8P50_200X102X55L30X30N]  (hidden comment: TC124-JR-0747KL)  (parts A,B,C,D of 4)
TP400  TPc120  [TESTPOINT_c120]  (value not drawn)  (no BOM)
TP401  TPc120  [TESTPOINT_c120]  (value not drawn)  (no BOM)
TP402  TPc120  [TESTPOINT_c120]  (value not drawn)  (no BOM)
TP403  TPc120  [TESTPOINT_c120]  (value not drawn)  (no BOM)
TP404  TPc120  [TESTPOINT_c120]  (value not drawn)  (no BOM)
TP409  TPc120  [TESTPOINT_c120]  (value not drawn)  (no BOM)
TP410  TPc120  [TESTPOINT_c120]  (value not drawn)  (no BOM)
TP417  TPc120  [TESTPOINT_c120]  (value not drawn)  (no BOM)
TP419  TPc120  [TESTPOINT_c120]  (value not drawn)  (no BOM)
TP428  TPc120  [TESTPOINT_c120]  (value not drawn)  (no BOM)
TP430  TPc120  [TESTPOINT_c120]  (value not drawn)  (no BOM)
TP431  TPc120  [TESTPOINT_c120]  (value not drawn)  (no BOM)
TP432  TPc120  [TESTPOINT_c120]  (value not drawn)  (no BOM)
TP433  TPc120  [TESTPOINT_c120]  (value not drawn)  (no BOM)
TP434  TPc120  [TESTPOINT_c120]  (value not drawn)  (no BOM)
TP435  TPc120  [TESTPOINT_c120]  (value not drawn)  (no BOM)
TP436  TPc120  [TESTPOINT_c120]  (value not drawn)  (no BOM)
TP437  TPc120  [TESTPOINT_c120]  (value not drawn)  (no BOM)
TP438  TPc120  [TESTPOINT_c120]  (value not drawn)  (no BOM)
TP439  TPc120  [TESTPOINT_c120]  (value not drawn)  (no BOM)
TP440  TPc120  [TESTPOINT_c120]  (value not drawn)  (no BOM)
U400  TPS259470ARPWR  [QFN16P45_200X200X100L15X25N]
U401  SN74LVC2G17DCKR  [SOT23-6P65_210X110L27X20N]  (parts A,B,C of 3)
X400a  AXF5G6012  [PANASONIC_AXF5G6012]
X400b  AXF5G6012  [PANASONIC_AXF5G6012]

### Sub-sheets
Nano_CAN_RS422 = 834834_ESCON2_EB_Nano_Nano-CAN-RS422.SchDoc: C_S2_/A (in), C_S2_A_HsDgin1 (in), C_S2_/B (in), C_S2_B_HsDgin2 (in), C_S2_I_HsDgin3 (in), C_CANH (bidir), C_CANL (bidir), CAN_ID1 (in), CAN_ID2 (in), CAN_ID3 (in), CAN_ID4 (in), CAN_ID5 (in), CAN_ID6 (in), CAN_AutoBR (in), S2_A_HsDgin1 (out), S2_B_HsDgin2 (out), S2_I_HsDgin3 (out), CAN_ID1_n (out), CAN_ID2_n (out), CAN_ID3_n (out), CAN_ID4_n (out), CAN_ID5_n (out), CAN_ID6_n (out), CAN_AutoBR_n (out), CAN_TX (bidir), CAN_RX (bidir), C_S2_Data_HsDgin4 (in), S2_Data_HsDgin4 (out)

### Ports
C_AnIN1+ (in), C_AnIN2+ (in), C_AnOUT1 (out), C_AnOUT2 (out), C_CANH (bidir), C_CANL (bidir), C_DigIN1 (in), C_DigIN2 (in), C_DigIN3 (in), C_DigIN4 (in), C_MotorTemp (in), C_S1_Hall1 (in), C_S1_Hall2 (in), C_S1_Hall3 (in), C_S2_/A (in), C_S2_/B (in), C_S2_A_HsDgin1 (in), C_S2_B_HsDgin2 (in), C_S2_Data_HsDgin4 (in), C_S2_I_HsDgin3 (in), C_USB_D+ (bidir), C_USB_D- (bidir), C_USB_VBUS, C_W1 (out), C_W2 (out), C_W3 (out), CAN_AutoBR (in), CAN_ID1 (in), CAN_ID2 (in), CAN_ID3 (in), CAN_ID4 (in), CAN_ID5 (in), CAN_ID6 (in), DBG_SWCLK (in), DBG_SWDIO (bidir), DigOUT1 (out), DigOUT2 (out), LED_Axis_gn (out), LED_Axis_rd (out), S2_Clock (out), SYS_/Reset (out), UART_RxD (in), UART_TxD (out)

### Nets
3V3: C420.2 D401.1(C) D402.1(C) U401.5(VCC) X400a.40 X400b.40
5V0: C413.2 C414.2 Q400.1(G) R421.2 R422.1 R423.2 TP417.1 U400.5(VIN) X400a.24 X400b.24
5V0_sensor1_2: R421.1 R429.2 TP404.1
C_VP: F400.1
GND: C400.2(-) C401.2(-) C405.1 C406.1 C407.1 C408.1 C409.1 C410.1 C411.1 C412.1 C413.1 C414.1 C415.1 C416.1 C417.1 C418.2 C419.2 C420.1 C421.1 D400.2(A) D403.2(A) D404.2(A) D405.1 D406.1 MP400.1 MP401.1 MP402.1 MP403.1 R406.1 R407.1 R408.1 R424.1 R425.1 R428.1 RN400.1 RN400.4 TP403.1 TP409.1 TP433.1 U400.8(GND) U401.2(GND) X400a.0b(0b_(NC)) X400a.10 X400a.11 X400a.49 X400a.50 X400a.55 X400a.57 X400a.59 X400b.0b(0b_(NC)) X400b.10 X400b.11 X400b.49 X400b.50 X400b.55 X400b.57 X400b.59
VP: C400.1(+) C401.1(+) C408.2 C409.2 C410.2 C411.2 C412.2 D400.1(C) F400.2 TP410.1 X400a.56 X400a.58 X400a.60 X400b.56 X400b.58 X400b.60
ADC_CB_Ident: R428.2 TP419.1 X400a.12 X400b.12
C_AnIN1+: D404.1(C) X400a.26 X400b.26 ; port C_AnIN1+
C_AnIN2+: D403.1(C) X400a.28 X400b.28 ; port C_AnIN2+
C_AnOUT1: D406.2 X400a.30 X400b.30 ; port C_AnOUT1
C_AnOUT2: D405.2 X400a.32 X400b.32 ; port C_AnOUT2
C_CANH: port C_CANH, sheet Nano_CAN_RS422/C_CANH
C_CANL: port C_CANL, sheet Nano_CAN_RS422/C_CANL
C_DigIN1: RN400.5 RN400.6 ; port C_DigIN1
C_DigIN2: RN400.7 RN400.8 ; port C_DigIN2
C_DigIN3: X400a.27 X400b.27 ; port C_DigIN3
C_DigIN4: X400a.29 X400b.29 ; port C_DigIN4
C_MotorTemp: C421.2 Q400.2(D) R427.2 ; port C_MotorTemp
C_S1_Hall1: X400a.13 X400b.13 ; port C_S1_Hall1
C_S1_Hall2: X400a.15 X400b.15 ; port C_S1_Hall2
C_S1_Hall3: X400a.17 X400b.17 ; port C_S1_Hall3
C_S2_/A: port C_S2_/A, sheet Nano_CAN_RS422/C_S2_/A
C_S2_/B: port C_S2_/B, sheet Nano_CAN_RS422/C_S2_/B
C_S2_A_HsDgin1: port C_S2_A_HsDgin1, sheet Nano_CAN_RS422/C_S2_A_HsDgin1
C_S2_B_HsDgin2: port C_S2_B_HsDgin2, sheet Nano_CAN_RS422/C_S2_B_HsDgin2
C_S2_Data_HsDgin4: port C_S2_Data_HsDgin4, sheet Nano_CAN_RS422/C_S2_Data_HsDgin4
C_S2_I_HsDgin3: port C_S2_I_HsDgin3, sheet Nano_CAN_RS422/C_S2_I_HsDgin3
C_USB_D+: X400a.46 X400b.46 ; port C_USB_D+
C_USB_D-: X400a.48 X400b.48 ; port C_USB_D-
C_USB_VBUS: X400a.44 X400b.44 ; port C_USB_VBUS
C_W1: C402.2 C405.2 L400.2 ; port C_W1
C_W2: C403.2 C406.2 L401.2 ; port C_W2
C_W3: C404.2 C407.2 L402.2 ; port C_W3
CAN_AutoBR: port CAN_AutoBR, sheet Nano_CAN_RS422/CAN_AutoBR
CAN_AutoBR_n: X400a.35 X400b.35 ; sheet Nano_CAN_RS422/CAN_AutoBR_n
CAN_ID1: port CAN_ID1, sheet Nano_CAN_RS422/CAN_ID1
CAN_ID1_n: X400a.37 X400b.37 ; sheet Nano_CAN_RS422/CAN_ID1_n
CAN_ID2: port CAN_ID2, sheet Nano_CAN_RS422/CAN_ID2
CAN_ID2_n: X400a.39 X400b.39 ; sheet Nano_CAN_RS422/CAN_ID2_n
CAN_ID3: port CAN_ID3, sheet Nano_CAN_RS422/CAN_ID3
CAN_ID3_n: X400a.41 X400b.41 ; sheet Nano_CAN_RS422/CAN_ID3_n
CAN_ID4: port CAN_ID4, sheet Nano_CAN_RS422/CAN_ID4
CAN_ID4_n: X400a.43 X400b.43 ; sheet Nano_CAN_RS422/CAN_ID4_n
CAN_ID5: port CAN_ID5, sheet Nano_CAN_RS422/CAN_ID5
CAN_ID5_n: X400a.45 X400b.45 ; sheet Nano_CAN_RS422/CAN_ID5_n
CAN_ID6: port CAN_ID6, sheet Nano_CAN_RS422/CAN_ID6
CAN_ID6_n: X400a.47 X400b.47 ; sheet Nano_CAN_RS422/CAN_ID6_n
CAN_RX: X400a.53 X400b.53 ; sheet Nano_CAN_RS422/CAN_RX
CAN_TX: X400a.51 X400b.51 ; sheet Nano_CAN_RS422/CAN_TX
DBG_SWCLK: X400a.34 X400b.34 ; port DBG_SWCLK
DBG_SWDIO: X400a.36 X400b.36 ; port DBG_SWDIO
DigIN1: TP430.1 U401.6(1Y) X400a.23 X400b.23
DigIN2: TP431.1 U401.4(2Y) X400a.25 X400b.25
DigOUT1: X400a.31 X400b.31 ; port DigOUT1
DigOUT2: X400a.33 X400b.33 ; port DigOUT2
LED_Axis_gn: X400a.21 X400b.21 ; port LED_Axis_gn
LED_Axis_rd: X400a.19 X400b.19 ; port LED_Axis_rd
MotorTemp: Q400.3(S) R427.1 TP432.1 X400a.42 X400b.42
S2_A_HsDgin1: X400a.14 X400b.14 ; sheet Nano_CAN_RS422/S2_A_HsDgin1
S2_B_HsDgin2: X400a.16 X400b.16 ; sheet Nano_CAN_RS422/S2_B_HsDgin2
S2_Clock: X400a.22 X400b.22 ; port S2_Clock
S2_Data_HsDgin4: X400a.20 X400b.20 ; sheet Nano_CAN_RS422/S2_Data_HsDgin4
S2_I_HsDgin3: X400a.18 X400b.18 ; sheet Nano_CAN_RS422/S2_I_HsDgin3
SYS_/Reset: X400a.38 X400b.38 ; port SYS_/Reset
U: L400.1 TP400.1 X400a.0a(0a_(NC)) X400a.1 X400a.2 X400a.4 X400b.0a(0a_(NC)) X400b.1 X400b.2 X400b.4
UART_RxD: X400a.54 X400b.54 ; port UART_RxD
UART_TxD: R418.1 ; port UART_TxD
UART_TxD_n: R418.2 TP428.1 X400a.52 X400b.52
V: L401.1 TP401.1 X400a.3 X400a.5 X400a.6 X400b.3 X400b.5 X400b.6
W: L402.1 TP402.1 X400a.7 X400a.8 X400a.9 X400b.7 X400b.8 X400b.9
NetC402_1: C402.1 R406.2 TP434.1
NetC403_1: C403.1 R407.2 TP435.1
NetC404_1: C404.1 R408.2 TP436.1
NetC415_2: C415.2 C416.2 R429.1 U400.6(OUT)
NetC417_2: C417.2 U400.7(DV/DT)
NetC418_1: C418.1 D401.2(A) RN400.3 TP439.1 U401.1(1A)
NetC419_1: C419.1 D402.2(A) RN400.2 TP440.1 U401.3(2A)
NetR422_2: R422.2 U400.1(EN/UVLO)
NetR423_1: R423.1 R424.2 TP437.1 U400.2(OVLO)
NetR425_2: R425.2 TP438.1 U400.9(ILM)

Not connected (* = marked no-connect by the designer): U400 3(AUXOFF)* 4(~{FLT})* 10(ITIMER)*

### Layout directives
net class NV: U, V, VP, W
net class HV: C_VP, C_W1, C_W2, C_W3, NetC402_1, NetC403_1, NetC404_1

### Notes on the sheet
- GND-Flächen zur Wämeableitung Modul --> EB

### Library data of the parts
C400 = CMP-001857-2: Polymer Hybrid Elco 47uF >=50V 20% D=8mm, H=10.8mm; Vibration proof: N; Ripple Current: 1.25A; Endurance: >=4'000h @105°C; Maximum Working Voltage: 50V; Case (Metric): F, D=8mm, H=10.8mm
C401 = CMP-001205-2: Polymer Hybrid Elco 22uF >=63V 20% D=6.3mm, H=8.3mm; Manufacturer: Nippon Chemi-Con; Maximum Working Voltage: 63V; Endurance: >=5'000h @105°C; Ripple Current: 1.5A; Value: 22µF; Case (Metric): D8, D=6.3mm, H=8mm; Vibration proof: N
C402-C404 = CMP-001930-1: 470pF C0G/NP0/X7R >=100V 20%; Manufacturer: X; Part Number: Ceramic, 0402, 470pF, 20%, >=100V, C0G/NP0/X7R, @, Soft Termination: N, -55°C to 125°C; Maximum Working Voltage: 100V; Case (Metric): 1005; Soft Termination: N
C405-C407 = CMP-001931-1: 220pF C0G/NP0/X7R >=100V 20%; Manufacturer: X; Part Number: Ceramic, 0402, 220pF, 20%, >=100V, C0G/NP0/X7R, @, Soft Termination: N, -55°C to 125°C; Case (Metric): 1005; Maximum Working Voltage: 100V; Soft Termination: N
C408-C412 = CMP-001034-2: 4.7uF X7R/X7S >=50V 20% >2.5uF@24V; Part Number: Ceramic, 1206, 4.7µF, 20%, >=50V, X7R/X7S, 2.5µF@24V, Soft Termination: Y, -55°C to 125°C; Manufacturer: X; Soft Termination: Y; Value: 4.7µF; Value@U: 2.5µF; Maximum Working Voltage: 50V; U@Value: 24V; Case (Metric): 3216
C413 = CMP-001146-2: 1uF X7R >=35V 20% Soft Termination; Manufacturer: X; Part Number: Ceramic, 0603, 1µF, 20%, >=35V, X7R, @, Soft Termination: Y, -55°C to 125°C; Soft Termination: Y; Maximum Working Voltage: 35V; Case (Metric): 1608
C414 C420 = CMP-000709-3: as C200 on sheet 834834_ESCON2_EB_Nano_Common-Components
C415 C421 = CMP-001306-1: as C202 on sheet 834834_ESCON2_EB_Nano_Common-Components
C416 = CMP-002059-1: 4.7uF X7R/X7S/X6S >=35V 20%; Part Number: Ceramic, 0805, 4.7µF, 20%, >=35V, X7R/X7S/X6S, @, Soft Termination: N, -55°C to 105°C; Case (Metric): 2012; Soft Termination: N; Maximum Working Voltage: 35V
C417 = CMP-000705-3: 1nF X7R >=50V 20%; Part Number: Ceramic, 0402, 1nF, 20%, >=50V, X7R, @, Soft Termination: N, -55°C to 125°C; Manufacturer: X; Soft Termination: N; Maximum Working Voltage: 50V; Case (Metric): 1005
C418 C419 = CMP-000706-3: 22pF C0G/NP0 >=50V 10%; Part Number: Ceramic, 0402, 22pF, 10%, >=50V, C0G/NP0, @, Soft Termination: N, -55°C to 125°C; Manufacturer: X; Case (Metric): 1005; Soft Termination: N; Maximum Working Voltage: 50V
D400 = CMP-001762-3: Transient Voltage Suppressor Diode, 28V V(RWM), Unidirectional, 200W, 1 Element, SOD-123F; Manufacturer: Littelfuse; Element Configuration: Single; Breakdown Voltage: 31.1V; Clamping Voltage: 45.4V; Polarity: Unipolar
D401 D402 = CMP-000606-13: as D201 on sheet 834834_ESCON2_EB_Nano_Common-Components
D403 D404 = CMP-001885-5: Transient Voltage Suppressor Diode, 5V V(RWM), Unidirectional, 1 Element, SOD882/DFN1006/0402/SOD-923F/SOD-923; Polarity: Unipolar; Max Junction Temperature: 150°C; Element Configuration: Single; Breakdown Voltage: 6.2V
D405 D406 = CMP-001117-7: Transient Voltage Suppressor Diode, 3.3V V(RWM), Bidirectional, 30W, 1 Element, SOD-882/DFN1006; Manufacturer: Nexperia; Element Configuration: Single; Breakdown Voltage: 4V; Polarity: Bipolar
F400 = CMP-001761-3: Electric Fuse, Very Fast Blow, 4A, 125VAC, 125VDC, 50A (IR), Clip Assembly; Manufacturer: Littelfuse; Maximum Working Voltage: 125V; Melting Integral: 3.152
L400-L402 = CMP-001760-3: Inductor Semi-Shielded, 33uH, 20%, I_RMS>2.3A, I_Sat>2.6A, R<120mOhm, 3131 (8080 Metric), 8.0x8.0mm, Height <=4.2mm; RMS Current: 2.3A; Shielding: Semi Shielded; Polarity: N; DC Resistance: 0.377; Case (Metric): 8080; Saturation Current: 2.6A
MP400 MP401 = CMP-001787-2: WA-SMST SMT Steel Spacer with internal Thread M2, L=1.5mm; Manufacturer: Wurth
MP402 MP403 = CMP-001785-2: WA-SMST SMT Steel Spacer with through hole Ø 2.25mm, L=1.5mm; Manufacturer: Wurth; Metric screw: M2
Q400 = CMP-001890-1: N-Channel MOSFET, 30V, 470mOhm, 0402/DFN1006/Picostar; pin to pad: 2>3 3>2; Element Configuration: N-CH
R406-R408 = CMP-000258-11: 390R 1% 100mW 100ppm; Part Number: Thick-Film, 0603, 390, 1%, 100mW@70°C, 75V, 100ppm, -55°C to 155°C; Manufacturer: X; Max Junction Temperature: 155°C; AECQ: N; Case (Metric): 1608; Power Rating Temperature: 70°C; Maximum Working Voltage: 75V; Maximum Overload Voltage: 150V
R418 = CMP-000173-11: as R204 on sheet 834834_ESCON2_EB_Nano_Common-Components
R421 = CMP-000466-10: as R210 on sheet 834834_ESCON2_EB_Nano_Common-Components
R422 = CMP-000221-11: 470k 1% 62.5mW 100ppm; Part Number: Thick-Film, 0402, 470k, 1%, 62.5mW@70°C, 50V, 100ppm, -55°C to 155°C; Manufacturer: X; Max Junction Temperature: 155°C; AECQ: N; Case (Metric): 1050; Power Rating Temperature: 70°C; Maximum Working Voltage: 50V; Maximum Overload Voltage: 100V
R423 = CMP-001891-1: 100k 0.1% 62.5mW 100ppm; Part Number: Thin-Film, 0402, 100k, 0.1%, 62.5mW@70°C, 50V, 100ppm, -55°C to 155°C; Manufacturer: X; Max Junction Temperature: 155°C; AECQ: N; Case (Metric): 1050; Power Rating Temperature: 70°C; Maximum Working Voltage: 50V; Maximum Overload Voltage: 100V
R424 = CMP-001674-2: 27k 0.1% 62.5mW 100ppm; Part Number: Thin-Film, 0402, 27k, 0.1%, 62.5mW@70°C, 50V, 100ppm, -55°C to 155°C; Manufacturer: X; Max Junction Temperature: 155°C; AECQ: N; Case (Metric): 1050; Power Rating Temperature: 70°C; Maximum Working Voltage: 50V; Maximum Overload Voltage: 100V
R425 = CMP-000497-12: 16k 1% 62.5mW 100ppm; Part Number: Thick-Film, 0402, 16k, 1%, 62.5mW@70°C, 50V, 100ppm, -55°C to 155°C; Max Junction Temperature: 155°C; AECQ: N; Case (Metric): 1050; Power Rating Temperature: 70°C; Maximum Working Voltage: 50V; Maximum Overload Voltage: 100V
R427 = CMP-000225-11: 1M 1% 62.5mW 100ppm; Part Number: Thick-Film, 0402, 1M, 1%, 62.5mW@70°C, 50V, 100ppm, -55°C to 155°C; Manufacturer: X; Case (Metric): 1050; Anti-Sulfur: N; Maximum Overload Voltage: 100V; Max Junction Temperature: 155°C; Maximum Working Voltage: 50V; Power Rating Temperature: 70°C
R428 = CMP-000492-11: as R213 on sheet 834834_ESCON2_EB_Nano_Common-Components
R429 = CMP-002057-1: 0R47 5% 62.5mW 1000ppm; Part Number: Thick-Film, 0402, 0.47, 5%, 62.5mW@70°C, 50V, 1000ppm, -55°C to 155°C; Manufacturer: X; Max Junction Temperature: 155°C; AECQ: N; Case (Metric): 1050; Power Rating Temperature: 70°C; Maximum Working Voltage: 50V; Maximum Overload Voltage: 100V
RN400 = CMP-002278-6: 4x47k 5% 62.5mW 200ppm 50V; Part Number: Thick-Film Concave/Convex, 4x0402, 47k, 5%, 62.5mW@70°C, 50V, 200ppm, -55°C to 125°C; AECQ: N; Case (Metric): 2010; Max Junction Temperature: 125°C; Maximum Overload Voltage: 100V; Power Rating Temperature: 70°C; Number of Elements: 4
TP400-TP404 TP409 TP410 TP417 TP419 TP428 TP430-TP440 = CMP-000014-7: Test Point; 1 pin, 1.20 mm D
U400 = CMP-001843-5: eFuse, 2.7V - 23V, 28mOhm, True Reverse Current Blocking, Input Reverse Polarity Protection, QFN10, 2mm x 2mm, 0.45mm Pitch; Manufacturer: TI; AECQ: N; Max Junction Temperature: 125°C; Element Configuration: Single; Polarity: Unipolar
U401 = CMP-001140-3: Dual, Schmitt Trigger, none inverting Buffer, 5V; Max Supply Voltage: 5.5V; Min Supply Voltage: 1.65V
X400a X400b = CMP-001692-7: Board to Board Connector, 2*30 pole, SMD, 0.4mm pitch, 1.5mm stacking Height; Manufacturer: Panasonic; Number of Contacts: 60; Operating Current: 500mA; Operating Voltage: 30V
